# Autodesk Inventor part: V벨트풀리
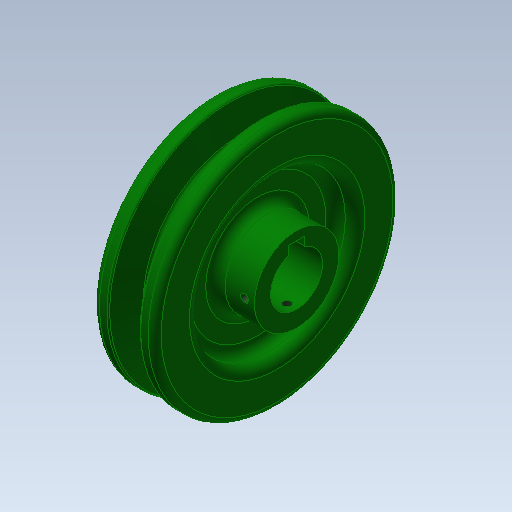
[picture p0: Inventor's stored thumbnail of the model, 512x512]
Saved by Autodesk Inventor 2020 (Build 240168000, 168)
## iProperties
Created: 2015-11
Part Number: V벨트풀리
Material: 강철, 탄소
Document SubType Name: Modeling
Designer: mduedu
Density: 1 g/cm^3
Appearance: 진녹색
Author: mduedu
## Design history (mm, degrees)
sketch "스케치1"
  geometry: L1 (-9.5, 0)-(9.5, 0); L2 (0, 0)-(0, 37.7); L3 (-4.825, 37.7)-(-9.5, 37.7); L4 (-9.5, 37.7)-(-9.5, 0); L5 (0, 28.7)-(-2.074, 28.7); L6 (-2.074, 28.7)-(-4.825, 37.7); L7 (4.825, 37.7)-(9.5, 37.7); L8 (9.5, 37.7)-(9.5, 0); L9 (0, 28.7)-(2.074, 28.7); L10 (2.074, 28.7)-(4.825, 37.7); L11 (-9.5, 35)-(9.5, 35); 3 further points
  constraints: 22 end point, 7 point on line, 4 perpendicular, 3 symmetric about line, 1 coincident, 1 horizontal, 1 horizontal alignment, 1 midpoint, 1 vertical
  dimensions: "d0" = 19 distance of L1.start L1.end; "d2" = 75.4 diameter of L2.end L1 (derived); "d3" = 34 deg angle of L10 L6; "d4" = 6.3 distance between parallel lines of L11 L9; "d5" = 2.7 distance between parallel lines of L7 L11; "d6" = 8 distance of point (4, 35) point (-4, 35); "d7" = 70 diameter of L11 L1
revolve "회전1" sketch "스케치1" stored, may be unused: angle "d8" = 90 deg
sketch "스케치2"
  geometry: C1 r 24 at (0, 0); C2 r 13 at (0, 0); 1 further point
  constraints: 2 centre point, 2 coincident
  dimensions: "d9" = 48 diameter of C1; "d10" = 26 diameter of C2
extrude "돌출1" cut sketch "스케치2" distance "d11" = 6; taper "d12" = 0 deg
extrude "돌출3" join sketch "스케치2" distance "d37" = 6; taper "d38" = 0 deg
fillet "모깎기1" dims "d13" = 3
fillet "모깎기2" dims "d14" = 3
fillet "모깎기3" dims "d15" = 1, "d16" = 0.5, "d17" = 2
hole "구멍1" diameter "d20" = 16; stored, may be unused: countersink angle "d24" = 90 deg, drill point angle "d26" = 118 deg; dims "d21" = 6, "d22" = 4, "d23" = 2, "d25" = 8, "d53" = 10, "d54" = 10
sketch "스케치3"
  geometry: L1 (-2.5, 0)-(2.5, 0); L2 (2.5, 0)-(2.5, 10.3); L3 (2.5, 10.3)-(-2.5, 10.3); L4 (-2.5, 10.3)-(-2.5, 0); 2 further points
  constraints: 8 end point, 2 parallel, 1 coincident, 1 horizontal, 1 midpoint, 1 perpendicular
  dimensions: "d27" = 5 distance of L2.end L3.end; "d29" = 10.3 distance of L3.end L1.start
extrude "돌출2" cut sketch "스케치3" extent not by distance; stored distance "d30" = 6; taper "d31" = 0 deg
node "작업 평면1"
sketch "스케치4"
  geometry: L1 (19, -27)-(19, 27) reference; 2 further points
  constraints: 1 horizontal alignment
  dimensions: "d52" = 22 distance from line of L1 point (-3, 0)
hole "구멍2" sketch "스케치4" at (-3, 0) diameter "d42" = 2.459; stored, may be unused: countersink angle "d46" = 90 deg, drill point angle "d48" = 118 deg; dims "d43" = 6, "d44" = 4, "d45" = 2, "d47" = 8
node "솔리드1"
mirror "대칭1"
pattern_circular "원형 패턴1" dims angle "d62" = 90 deg
